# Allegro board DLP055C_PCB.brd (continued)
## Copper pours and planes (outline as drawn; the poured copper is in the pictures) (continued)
P1P8V on LY3: 183.64,48.77 175.98,48.77 173.67,46.46 173.67,42.67 173.88,42.47 173.88,42.21 172.73,41.07 170.12,41.07 168.44,42.75 168.44,53.59 178.83,63.98 178.83,84.38 178.12,85.09 160.34,85.09 159.5,85.93 159.5,90.17 160.31,90.98 161.56,90.98 161.63,90.91 165.52,90.91 166.7,92.08 166.7,103.84 167.56,104.71 183.64,104.71
P1P8V on LY8_PLANE: 146.02,79.87 148.51,79.87 150.03,78.34 151.81,78.34 153.72,80.25 158.03,80.25 160.7,82.91 160.7,87.74 161.97,89.01 161.97,90.53 160.32,92.19 160.32,94.6 158.8,96.12 152.95,96.12 152.07,97.01 152.07,97.9 152.7,98.54 152.7,99.3 152.32,99.68 151.81,99.68 151.3,99.17 151.3,94.98 151.68,94.6 157.15,94.6 158.03,93.71 158.03,91.04 155.62,88.63 155.62,87.74 157.4,85.96 157.4,83.55 155.11,81.26 150.29,81.26 149.4,82.15 149.4,83.3 149.27,83.42 144.83,83.42 143.94,84.31 143.94,86.34 147.11,89.52 147.11,90.28 146.6,90.79 145.97,90.79 145.08,89.9 143.43,89.9 143.3,90.03 143.3,91.3 145.33,93.33 145.33,94.09 144.45,94.98 143.05,94.98 141.3,93.23 141.3,80.65 138.86,78.22 138.86,68.08 139.62,67.32 141.55,67.32 145.36,71.13 145.36,79.21
P1P15V on TOP: 167.37,58.27 167.37,67.44 167.35,67.46 158.46,67.46 158.33,67.34 158.33,61.11 158.69,60.76 163.94,60.76 164.63,60.07 164.63,58.45 164.81,58.27
P1P15V on TOP: 146.15,80.32 159.28,80.32 160.42,81.47 160.42,96.35 158.95,97.82 148.48,97.82 147.62,96.96 147.62,94.14 148.48,93.28 155.37,93.28 155.83,92.82 155.83,84.9 155.47,84.54 153.72,84.54 153.62,84.64 147.85,84.64 146.15,82.94
P1P15V on BOTTOM: 165.53,52.69 166.29,52.69 166.67,53.07 166.67,54.97 167.18,55.48 173.27,55.48 173.53,55.74 173.53,56.12 170.99,58.66 170.23,58.66 168.96,59.93 168.96,65.01 166.54,67.42 161.72,67.42 158.67,64.37 158.67,61.07 159,60.74 163.22,60.74 165.4,58.56 165.4,52.82
P1P15V on LY7_PLANE: 145.86,59.94 164.78,59.94 166.29,61.45 166.29,105.52 161.57,110.24 151.32,110.24 141.67,100.58 141.67,87.63 142.83,86.47 146.73,86.47 147.11,86.85 147.11,87.11 146.86,87.36 146.22,87.36 145.08,88.5 145.08,90.28 149.67,94.87 154.46,94.87 154.99,94.34 154.99,91.17 155.62,90.53 157.29,90.53 157.53,90.3 157.53,89.39 156.76,88.63 155.49,88.63 154.29,87.42 154.29,77.14 150.18,73.03 139,73.03 137.86,71.88 137.86,67.94
P1P15V_BST on TOP: 159.83,54.79 159.83,56.54 159.6,56.77 158.92,56.77 158.92,54.94 159.07,54.79
P1P15V_FET on BOTTOM: 167.3,55.17 173.37,55.17 173.55,54.99 173.55,54.53 173.39,54.38 167.27,54.38 167.14,54.51 167.14,55.02
P1P15V_SW on TOP: 160.64,55.09 160.64,56.9 161.15,57.4 163.49,57.4 163.66,57.58 163.66,60.07 163.59,60.15 158.41,60.15 158.33,60.07 158.33,57.51 158.51,57.33 159.42,57.33 159.98,56.77 159.98,55.09
P1P21V on TOP: 83.64,54.31 93.62,54.31 96.06,56.75 96.06,80.88 100.03,84.86 100.03,87.5 98.47,89.06 96.34,89.06 90.47,83.19 90.47,57.11 89.89,56.52 83.71,56.52 83.64,56.45
P1P21V on BOTTOM: 159.88,81.91 159.88,87.56 157.85,89.59 157.85,90.14 158.2,90.48 159.55,90.48 159.88,90.82 159.88,97.86 158.92,98.81 140.15,98.81 134.18,92.84 134.18,82.8 134.75,82.23 137,82.23 137.38,81.85 139.47,81.85 139.47,85.89 140.03,86.45 141.32,86.45 141.91,85.86 141.91,85.4 140.46,83.96 140.46,81.85 148.87,81.85 148.87,85.4 147.98,85.4 147.39,85.99 147.39,92.85 147.9,93.35 154.22,93.35 154.71,92.87 154.71,85.18 154.15,84.62 152.4,84.62 152.4,80.3 158.26,80.3
P1P21V on LY7_PLANE: 137.35,82.8 137.35,78.99 138.49,77.85 144.34,77.85 147.75,81.26 147.75,87.36 147.49,87.61 146.35,87.61 145.48,88.49 145.48,90.3 149.67,94.49 154.34,94.49 154.73,94.09 154.73,90.53 154.99,90.28 156.76,90.28 157.02,90.03 157.02,89.65 156.51,89.14 154.48,89.14 153.84,88.5 153.84,77.98 149.65,73.79 131.76,73.79 128.97,76.58 128.97,81.41 125.92,84.45 96.84,84.45 96.46,84.84 96.46,89.53 96.96,90.04 130.11,90.04
P2P5V on TOP: 49.2,79.87 50.97,79.87 51.23,80.12 51.23,83.17 50.21,84.18 48.56,84.18 48.05,83.68 48.05,82.03 49.2,80.88
P2P5V on TOP: 84.12,58.15 87.8,58.15 88.57,58.91 88.57,76.06 88.06,76.56 86.53,76.56 86.15,76.18 86.15,75.17 86.79,74.53 86.79,66.91 82.72,62.85 82.72,59.55
P2P5V on LY3: 87.17,73.26 87.93,73.26 88.82,74.15 88.82,75.55 87.93,76.44 84.63,76.44 83.87,75.68 59.1,75.68 50.59,84.18 48.18,84.18 47.67,83.68 47.67,82.41 57.2,72.88 86.79,72.88
P3P3V on TOP: 51.74,82.79 53.89,82.79 54.02,82.91 54.02,83.93 55.16,85.07 55.16,86.6 54.53,87.23 52.75,87.23 51.74,86.22 50.21,86.22 50.08,86.09 50.08,84.95 51.74,83.3
P3P3V on LY8_PLANE: 0.76,150.59 65.96,150.59 66.1,150.45 66.8,150.45 66.94,150.59 69.95,150.59 70.09,150.45 70.63,150.45 70.77,150.59 78.99,150.59 78.99,148.99 81.36,148.99 81.36,150.59 83.74,150.59 83.74,148.99 86.11,148.99 86.11,150.59 187.34,150.59 187.34,0.76 0.76,0.76 0.76,17.71 1.11,18.06 1.11,19.95 0.76,20.3 0.76,42.66 0.94,42.83 0.94,45.02 0.76,45.2
P3P3V_SB on TOP: 87.31,124.79 87.31,123.93 87.24,123.85 87.24,123.14 86.7,122.61 80.94,122.61 80.68,122.35 80.68,116.15 81.34,115.49 87.97,115.49 88.02,115.54 88.02,118.57 87.92,118.67 87.92,120.42 88.15,120.65 88.15,123.29 87.59,123.85 87.59,124.79
P3P3V_SB on TOP: 167.02,133.45 168.47,133.45 169.02,134.01 169.02,137.24 168.74,137.52 167.25,137.52 166.79,137.06 166.79,133.68
P3P3V_SB on LY7_PLANE: 2.35,2.63 2.35,146.05 6.41,150.11 77.91,150.11 78.99,149.04 78.99,148.99 79.04,148.99 91.63,136.4 91.63,69.92 110,51.55 163.37,51.55 174.94,63.12 174.94,111.25 165.93,120.27 165.93,136.4 166.56,137.03 169.48,137.03 170.62,135.89 170.62,130.94 171.51,130.05 177.61,130.05 185.74,121.92 185.74,2.63
USB_AUX on TOP: 86.58,127 86.58,128.22 85.99,128.8 85.99,129.77 85.79,129.97 82.64,129.97 82.61,129.95 82.61,128.14 82.92,127.84 85.33,127.84 86.17,127
USB_SW on TOP: 86.6,124.82 80.68,124.82 80.68,122.89 85.36,122.89 85.56,123.09 85.56,123.95 85.79,124.18 86.6,124.18
USB_VBUS on TOP: 87.08,127 87.08,128.63 88.15,129.69 88.15,138.99 87.9,139.24 85.59,139.24 85.2,138.86 85.2,130.99 86.22,129.97 86.22,129.01 86.86,128.37 86.86,127
N30120583 on TOP (solid shape): 76.63,57.83 76.63,57.21 76.81,57.03 78,57.03 81.26,53.78 85.37,53.78 87.88,51.27 87.88,47.2 82.5,47.2 81.8,47.9 81.8,50.97 76.69,56.08 75.29,56.08 73.96,57.41 73.96,57.42 73.68,57.72 73.27,57.64 73.09,57.64 73.02,57.71 71.97,57.71 71.89,57.78 71.89,57.89 71.92,57.91 72.94,57.91 73.29,58.26 76.2,58.26
N30120672 on TOP (solid shape): 74.43,55.8 76.1,55.8 79.14,52.76 79.14,51.29 76.97,51.29 73.27,54.99 73.27,56.41 72.96,56.72 71.67,56.72 71.62,56.77 71.62,56.9 71.64,56.92 73.32,56.92
N30120689 on TOP (solid shape): 72.66,54.91 76,51.57 76,51.03 76.07,50.96 76.61,50.96 77.07,50.5 77.87,50.5 78.84,49.54 78.84,45.34 78.78,45.24 78.67,45.26 77.97,44.92 78.67,44.58 78.78,44.59 78.84,44.5 78.84,44.25 78.78,44.16 78.68,44.16 77.99,43.81 78.68,43.47 78.78,43.47 78.84,43.38 78.84,40.12 78.13,39.4 77.06,39.4 76.35,40.12 76.35,48.09 74.14,50.3 73.46,50.3 72.61,51.16 72.61,53.75 71.36,54.99 71.36,56.29 71.46,56.39 72.66,56.39
N30120771 on TOP: 82.98,39.61 90.09,39.61 90.47,39.99 90.47,41.89 89.84,42.53 83.61,42.53 83.1,43.04 81.96,43.04 81.58,42.66 81.58,41
N30121099 on TOP (solid shape): 79.8,62.34 78.42,60.95 78.38,60.97 77.92,60.87 77.83,60.41 77.84,60.37 77.75,60.28 75.99,60.28 75.91,60.2 74.42,60.2 74.41,60.2 74.24,60.24 74.07,60.2 74.06,60.2 71.74,60.2 71.74,60.43 72.91,60.43 73.04,60.56 73.58,60.56 75.44,62.42 75.46,62.43 75.66,62.54 75.78,62.75 75.78,62.76 76.63,63.61 79.8,63.61
N30121105 on TOP (solid shape): 82.93,56.55 82.93,54.57 82.7,54.34 81.43,54.34 80.23,55.54 80.69,55.54 80.69,55.48 80.7,55.42 80.72,55.36 80.74,55.31 80.77,55.26 80.81,55.21 80.85,55.17 80.9,55.14 80.95,55.11 81.01,55.09 81.07,55.08 81.13,55.08 81.18,55.08 81.24,55.09 81.3,55.11 81.35,55.14 81.4,55.17 81.44,55.21 81.48,55.26 81.51,55.31 81.53,55.36 81.55,55.42 81.56,55.48 81.56,55.54 81.55,55.6 81.53,55.65 81.51,55.71 81.48,55.76 81.44,55.8 81.4,55.84 81.35,55.88 81.3,55.91 81.24,55.93 81.18,55.94 81.13,55.94 81.07,55.94 81.01,55.93 80.95,55.91 80.9,55.88 80.85,55.84 80.81,55.8 80.77,55.76 80.74,55.71 80.72,55.65 80.7,55.6 80.69,55.54 80.23,55.54 78.25,57.51 77.01,57.51 77.01,59.04 77.92,59.95 79.52,59.95
N30121238 on TOP: 52.88,65.01 55.29,65.01 55.67,65.39 55.67,67.17 50.59,72.25 50.59,73.14 50.34,73.39 49.83,73.39 49.58,73.14 49.58,68.31
N30121264 on TOP: 42.97,65.01 47.93,65.01 48.69,65.77 48.69,69.33 47.93,70.09 45.51,70.09 42.97,67.55
N30121264 on BOTTOM: 46.66,66.79 56.56,66.79 57.58,67.8 63.04,67.8 65.07,65.77 65.58,65.77 65.83,66.02 65.83,66.91 62.53,70.21 47.67,70.21 46.15,68.69 46.15,67.29
N30121280 on TOP: 49.7,74.53 50.47,74.53 50.97,75.04 50.97,78.47 51.1,78.6 51.1,79.23 50.97,79.36 49.2,79.36 48.94,79.1 48.94,78.6 49.32,78.22 49.32,75.42 49.7,75.04
N30121351 on TOP (solid shape): 72.5,43.38 72.5,41.65 77,37.15 77,33.22 76.8,33.01 76.01,33.01 70.88,38.14 70.88,43.55 71.26,43.93 71.95,43.93
N30121367 on TOP (solid shape): 53.39,78.6 53.39,77.86 54.66,76.59 54.66,72.22 57.12,69.76 61.51,69.76 62.3,68.97 62.94,68.97 62.94,68.03 56.18,68.03 51.74,72.48 51.74,77.3 52.37,77.94 52.37,78.65 53.34,78.65
N30121469 on TOP (solid shape): 80.66,34.52 80.66,32.97 80.23,32.54 78.83,32.54 77.64,33.73 77.64,34.47 77.89,34.72 80.45,34.72
N30121485 on TOP (solid shape): 70.62,49.83 70.62,48.89 70.66,48.85 70.66,46.15 70.07,45.57 70.07,39.52 66.35,35.8 61.59,35.8 61.59,37.04 67.73,43.18 67.73,44.85 68.54,45.66 68.74,45.66 69.69,46.62 69.69,48.93 69.64,48.98 69.64,50.5 69.95,50.5
N30121491 on TOP (solid shape): 64.83,74.77 64.83,71.62 66.18,70.27 67.17,70.27 67.83,69.61 67.83,67.89 67.74,67.79 67.74,65.52 67.62,65.41 67.62,65.23 67.62,65.22 67.62,64.81 67.46,64.65 67.46,63.1 67.38,63.03 67.26,63.15 67.26,64.78 67.31,64.99 67.26,65.2 67.26,66.28 66.28,67.25 66.28,68.62 62.04,72.86 62.04,75.02 62.12,75.1 64.5,75.1
N30121519 on TOP (solid shape): 70.35,53.13 70.42,53.22 70.53,53.2 72.28,51.44 72.28,45.31 71.87,44.9 71.21,44.9 70.9,45.2 70.9,45.86 71.29,46.25 71.29,50.06 71.11,50.23 71.08,50.33 71.15,50.4 71.51,51.33 70.53,51.47 70.42,51.45 70.35,51.55
N30121523 on TOP (solid shape): 66.49,66.71 66.49,65.19 66.49,65.18 66.44,64.99 66.49,64.8 66.49,64.79 66.49,63 66.44,62.95 66.37,62.95 66.26,63.05 66.26,64.58 66.15,64.69 66.15,66.04 64.18,68 63.83,68 63.83,68.94 64.26,68.94
N30122241 on TOP (solid shape): 58.92,53.68 61.79,53.68 61.79,52.86 60.68,51.75 60.68,49.87 59.58,48.77 56.43,48.77 56.43,54.06 58.54,54.06
N30122253 on TOP (solid shape): 63.69,56.85 63.69,56.72 63.67,56.69 62.19,56.69 61.77,56.27 61.77,54.21 59.66,54.21 59.66,55.41 61.18,56.92 63.61,56.92
N30122298 on TOP (solid shape): 60.99,57.55 61.38,57.55 61.38,57.55 62.21,57.55 62.33,57.43 63.39,57.43 63.49,57.33 63.49,57.2 62.28,57.2 62.21,57.13 61.06,57.13 58.49,54.57 55.24,54.57 53.41,52.74 53.41,48.78 51.86,48.78 51.86,54.01 53.73,55.88 56.53,55.88 56.98,56.34 56.98,57.99 60.56,57.99
N30122422 on TOP (solid shape): 68.29,85.78 68.29,79.3 68.97,78.61 68.97,75.79 68.87,75.69 68.8,75.77 68.8,77.39 68.03,78.16 66.59,78.16 65.93,78.82 65.93,81.58 66.56,82.22 66.56,85.6 67.17,86.21 67.86,86.21
N30122488 on TOP (solid shape): 73.04,70.71 73.04,69.34 72.8,69.11 72.78,69.11 72.39,69 72.27,68.6 72.27,68.58 71.87,68.17 71.92,68.12 71.92,66.85 71.62,66.55 70.65,66.55 69.54,65.44 69.54,64.48 69.48,64.42 69.48,63.17 69.43,63.12 69.28,63.12 69.28,64.41 69.18,64.52 69.18,66.24 69.46,66.52 69.46,70.1 70.29,70.94 72.81,70.94
N30122494 on TOP (solid shape): outline of 85 points within 69.74,72.12 77.01,79.61
N30122512 on TOP (solid shape): 84.91,68.72 83.66,67.47 81.71,67.47 80.26,66.02 80.26,65.4 80.1,65.24 77.78,65.24 77.73,65.19 77.66,65.16 77.59,65.18 76.91,65.24 76.72,64.59 76.71,64.49 76.63,64.45 75.78,64.45 75.36,64.65 74.94,64.45 72.96,64.45 72.46,64.78 71.97,64.45 69.77,64.45 69.72,64.5 69.72,65.21 70.63,66.13 76.42,66.13 77.42,67.12 77.42,67.41 78.15,68.14 78.25,68.17 78.32,68.1 78.84,67.78 79.24,68.24 79.24,68.55 80.73,68.55 82.23,70.06 84.91,70.06
N30122563 on TOP (solid shape): 85.17,78.05 85.17,73.02 83.95,71.8 80.37,71.8 79.86,71.29 78.54,71.29 78.11,71.72 78.11,73.4 78.34,73.63 79.66,73.63 81.67,75.63 84.26,75.63 84.26,77.72 82.17,77.72 82.17,75.63 81.67,75.63 81.69,75.66 81.69,77.69 82.33,78.33 84.89,78.33
N30126115 on TOP: 12.74,41.35 17.16,41.35 19.34,43.54 21.07,43.54 21.37,43.84 21.37,45.44 21.76,45.82 21.76,46.53 21.6,46.69 19.67,46.69 17.13,44.15 13.91,44.15 12.38,42.62 12.38,41.71
N30126127 on TOP: 19.85,47.35 21.58,47.35 21.81,47.57 21.81,48.23 22.64,49.07 24.09,49.07 24.19,49.17 24.07,49.3 20.89,49.3 19.7,48.11 19.7,47.5
N30126180 on TOP: 14.57,62.28 17.08,62.28 19.32,64.52 22.85,64.52 23.33,65 26.45,65 26.86,65.41 26.86,65.81 26.25,66.42 16.12,66.42 14.36,64.67 14.36,62.48
N30126190 on TOP: 12.69,45.92 16.83,45.92 20.41,49.5 22.85,49.5 22.92,49.58 24.19,49.58 24.3,49.68 24.19,49.78 22.75,49.78 22.62,49.91 20.89,49.91 20.05,50.75 18.12,50.75 17.44,50.06 17.44,49.2 17.18,48.95 14.24,48.95 12.46,47.17 12.46,46.15
N30126220 on TOP: 29.6,55.55 29.6,58.13 29.13,58.61 28.65,58.61 28.32,58.94 28.32,61.17 28.06,61.43 28.06,63.25 24.63,63.25 24.63,61.81 25.88,60.56 25.88,58.81 26.16,58.53 27.28,58.53 27.66,58.15 28.05,58.15 29.4,56.79 29.4,55.6 29.45,55.55
N30126331 on TOP: 29.96,55.19 30.04,55.19 30.11,55.27 30.11,56.95 31.21,58.05 31.21,60.94 32.46,62.19 32.46,63.27 28.85,63.27 28.85,60.7 28.88,60.67 28.88,59.14 29.91,58.11 29.91,55.25
N30126337 on TOP: 28.66,72.26 24.3,72.26 23.84,71.81 23.84,69.22 25.06,68 29.12,68 29.12,65.35 29.38,65.1 31.79,65.1 32.32,65.63 32.32,66.14 31.1,67.36 31.1,69.82
N30126360 on TOP: 30.62,55.63 30.62,56.82 30.68,56.88 33.63,56.88 35.7,54.81 35.7,52.73 36,52.43 38.19,52.43 38.62,52.86 38.62,53.42 38.04,54 38.04,56.29 37.25,57.07 35.95,57.07 34.93,58.1 31.54,58.1 30.39,56.95 30.39,55.63 30.47,55.55 30.54,55.55
N30126390 on TOP: 36.11,39.95 39.08,39.95 39.69,40.56 39.69,42.72 37.43,44.98 37.43,47.68 38.8,49.05 38.8,50.04 38.32,50.52 35.8,50.52 35.42,50.14 35.42,40.64
N30128736 on TOP: 60.87,90.32 65.01,90.32 67.17,92.48 67.81,92.48 67.83,92.46 68.47,92.46 68.87,92.86 68.87,94.31 69.33,94.77 69.33,95.86 69.02,96.16 67.48,96.16 67.09,95.78 67.09,94.84 65.7,93.45 62.45,93.45 60.31,91.31 60.31,90.88
N30128748 on TOP: 67.6,96.88 68.9,96.88 70.62,98.6 72.56,98.6 72.68,98.73 72.58,98.83 68.87,98.83 67.35,97.31 67.35,97.13
N30128801 on TOP: 71.26,114.5 73.95,114.5 74.13,114.68 74.13,115.65 73.14,116.64 73.14,123.01 71.44,124.71 68.8,124.71 68.41,124.33 68.41,122.17 71.77,118.82 71.77,116.18 70.88,115.29 70.88,114.88
N30128811 on TOP: 61,94.92 63.56,94.92 67.63,98.98 69.08,98.98 69.18,99.09 72.4,99.09 72.5,99.19 72.38,99.31 68.97,99.31 68.52,99.77 63.97,99.77 63.44,99.24 63.44,98.45 62.47,97.49 61.18,97.49 60.06,96.37 60.06,95.86
N30128841 on TOP: 77.86,105.05 77.86,107.37 77.19,108.04 76.12,108.04 75.21,108.95 75.21,111.88 74.23,112.85 71.36,112.85 71.01,112.51 71.01,111.64 71.24,111.41 71.73,111.41 72.87,110.27 72.87,108.55 73.96,107.45 75.13,107.45 75.49,107.09 77.25,107.09 77.64,106.71 77.64,105.16 77.74,105.05
N30128952 on TOP: 78.35,105.13 78.35,107.87 79.29,108.81 79.29,111.23 79.87,111.81 79.87,112.24 79.46,112.65 77.08,112.65 76.54,112.12 76.54,109.42 78.17,107.8 78.17,105.16 78.27,105.05
N30128958 on TOP: 77.08,114.5 79.69,114.5 80.07,114.88 80.07,115.54 78.68,116.94 78.68,124.16 77.99,124.84 75.15,124.84 74.64,124.33 74.64,121.69 75.98,120.35 76.54,120.35 77.43,119.46 77.43,116.41 76.75,115.72 76.75,114.83
N30128978 on TOP: 78.73,104.8 78.78,104.8 78.88,104.9 78.88,106.43 79.01,106.55 81.72,106.55 83.55,104.72 85.28,104.72 85.79,105.23 85.79,107.19 85.2,107.77 85.2,111.38 84.95,111.63 84.21,111.63 83.78,111.2 83.78,107.95 83.12,107.29 78.93,107.29 78.65,107.01 78.65,104.98 78.63,104.95 78.63,104.9
N30129011 on TOP: 87.44,108.2 88.51,108.2 90.51,110.21 97.4,110.21 98.51,111.33 98.51,114.33 98.13,114.71 94.2,114.71 90.97,111.48 87.21,111.48 86.96,111.23 86.96,108.69
N30131580 on TOP: 35.99,128.89 39.04,128.89 39.54,129.4 39.54,131.68 39.92,132.06 46.66,132.06 49.96,128.76 53.39,128.76 53.89,129.27 53.89,131.68 54.4,132.19 54.4,133.84 56.94,136.38 56.94,137.4 56.69,137.65 55.67,137.65 54.4,136.38 49.2,136.38 48.05,137.52 48.05,141.21 47.67,141.59 47.04,141.59 46.27,140.83 46.27,136.76 44.5,134.98 37,134.98 35.99,133.97
N30131717 on TOP: 33.19,139.94 29.26,139.94 26.97,137.65 26.97,129.02 27.99,128 31.92,128 33.45,129.52 33.45,139.68
N30131961 on TOP: 29.38,140.7 33.45,140.7 38.02,145.27 38.02,148.45 37.26,149.21 29.89,149.21 27.73,147.05 27.73,142.35
N30131963 on TOP: 25.07,137.78 26.84,137.78 27.48,138.41 27.48,143.62 23.03,148.07 19.99,148.07 19.1,147.18 19.1,143.75
N30131977 on TOP: 63.16,128.17 64.2,128.17 64.63,128.6 64.63,130.66 65.19,131.22 66.69,131.22 66.99,131.52 66.99,134.06 66.46,134.59 63.56,134.59 62.57,133.6 62.57,130.17 63.03,129.72 63.03,128.3
N30132682 on TOP: 165.21,144.63 166,144.63 168.03,146.66 168.03,148.87 167.93,148.97 165.6,148.97 164.63,148.01 164.63,145.21
N30132740 on TOP: 164.27,142.7 164.27,140.05 164.51,139.81 164.51,139.18 164,138.67 164,133.33 164.26,133.08 164.26,131.94 164.69,131.5 165.38,131.5 165.38,132.8 165.78,133.21 165.78,137.78 166.04,138.03 168.86,138.03 169.13,138.3 169.13,142.88 168.36,143.64 165.21,143.64
N30132740 on BOTTOM: 162.38,129.5 163.52,129.5 164.87,128.15 166.98,128.15 166.98,130.13 166.54,130.56 165.83,130.56 165.38,131.02 165.38,135.01 164.77,135.62 164.38,135.62 163.95,135.19 163.95,132.55 162.1,130.69 162.1,129.78

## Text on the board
BOTTOM: LAYER 14 - BOTTOM
Ref Des/Silkscreen Bottom: LIBRA# DLP055
TOP: LAYER 1 - TOP
Ref Des/Silkscreen Top: FAN | DUAL CONTROLLER | MD1 | MD0 | ON | MD2 | USB | PARALLEL | CWI1 | VX1 | IIC0 | IIC1 | LOCK | CWI2 | TSTPTS | CWI0 | SPI1 | UART0 | FPDLINK | COIL1 | COIL2 | IIC2 | 12V FAN | DMD_HSSI0 | HEART  BEAT | FAULT | DMD_HSSI1 | ACTUATOR I/F | MADE IN U.S.A
L2_GND: LAYER 2 - GND PLANE
LY3: LAYER 3 - SIGNAL
LY4_GND: LAYER 4 - GND PLANE
LY5: LAYER 5 - SIGNAL
LY6_GND: LAYER 6 - GND PLANE
LY7_PLANE: LAYER 7 - PWR PLANE
LY8_PLANE: LAYER 8 - PWR PLANE
LY9_GND: LAYER 9 - GND PLANE
LY10: LAYER 10 - SIGNAL
LY11_GND: LAYER 11 - GND PLANE
LY12: LAYER 12 - SIGNAL
L13_GND: LAYER 13 - GND PLANE
DISPLAY_TOP: SOLDERPASTE TOP
User.6: SOLDERPASTE BOTTOM
User.7: LINE WIDTH (MILS) | LINE WIDTH/SPACING (MILS) | PCB MUST BEAR THE UL94V-0 UL REGISTERED MATERIAL ID NUMBER. | ACTUAL FABRICATION DATA MUST BE REVIEWED AND APPROVED. | 4. ALL BOARDS MUST MEET OR EXCEED UL94V-0 REQUIREMENTS. | 5. MINIMUM COPPER WALL THICKNESS OF PLATED-THRU | HOLES TO BE .001 INCH, WITH A MINIMUM | ANNULAR RING OF .001 INCH. | 6. OVERALL BOARD THICKNESS TO BE .076 +/- 10% | AND APPLIES AFTER ALL LAMINATION AND PLATING | PROCESSES, MEASURED FROM COPPER TO COPPER. | 7. MAX. WARP & TWIST TO BE .0075 INCHES PER INCH. | 8. ANY DESCREPENCY BETWEEN FABRICATION PRINT AND THE | FAB NOTES: | 2. THE PWB SHALL BE FABRICATED TO IPC-6012, | CLASS 2 AND WORKMANSHIP SHALL CONFORM TO | IPC-A-600, CLASS 2. CURRENT REVISIONS. | ROHS TO BE MARKED ON THE FINISHED BOARD. | 1. ALL DIMENSIONS ARE IN INCHES UNLESS | OTHERWISE NOTED.  ALL BOARD | OUTLINE DIMENSION TOLERANCES ARE +/- 10%. | BOARD OUTLINE DIMENSIONS ARE FOR REFERENCE ONLY | SEE GERBER FILES FOR EXACT BOARD OUTLINE DIMENSIONS. | 3. BOARD MATERIAL SHALL BE 180 Tg/340 Td ISOLA FR-370HR | OR EQUIVALENT, RoHS COMPLIANT AND LEAD FREE | ASSEMBLY CAPABLE.  BOARD MATERIAL SHALL | MEET OR EXCEED IPC-4101B. RoHS CERTIFICATE OF | CONFORMANCE SHALL BE DELIVERED WITH EACH LOT. | FABRICATION VENDOR IS ALLOWED TO INCREASE SOLDERMASK | COMPONENT PADS BY A MAXIMUM 1 MIL ON EACH SIDE OVER | THE COPPER PAD IN ORDER TO MEET TOOLING REQUIREMENTS | WHILE MAINTAINING WEBBING BETWEEN ADJACENT PADS. | 4. APPLY LPI SILKSCREEN OR EQUIVALENT PER THE ARTWORK | BOTH SIDES.  COLOR: WHITE. | NICKEL 100 MICROINCHES THK MIN, GOLD 2-6 MICROINCHES THK. | LAYER | 1 | 3 | 5 | 10 | 12 | 14 | 50 OHMS | 7.5 | 4.8 | IMPEDANCE REQUIREMENTS +/- 10% | 100 OHMS DIFFERENTIAL | 4.5/7.25 | 5/7 | 90 OHMS DIFFERENTIAL | 6/6 | 5.2/5.8 | PREPREG | CORE | 2 | 4 | 6 | 7 | 8 | 9 | 11 | 13 | DEFINITION | GND PLANE | SIGNAL | SOLDERMASK | SILKSCREEN | SPLIT PLANE | PREPREG/CORE | THICKNESS | (MILS) | 1 OZ | 1/2 OZ | Cu WT. | 0 | FAB DWG | + | 10% | 0.076 | - | TOP SIDE VIEW | LAYER STACKUP
User.15: DLPC7540EVM FORMATTER BOARD | DLP055 | TEXAS INSTRUMENTS | 16-APR 2021 | C
User.34: FIGURE | SIZE | 8.0 | 12.0 | 28.0 | 36.0 | 38.0 | 40.0 | 42.0 | 45.0 | 50.0 | 63.0 | 90.0 | 126.0 | 59.0 | 135.0 | 33.5x25.6 | 59.06x32.68 | 118.11x40.0 | 140.0x40.0 | 300.0x100.0 | DRILL CHART: TOP to BOTTOM | ALL UNITS ARE IN MILS | TOLERANCE | +0.0/-8.0 | +0.0/-12.0 | +3.0/-3.0 | +2.99/-2.99 | PLATED | NON-PLATED | QTY | 2451 | 35 | 127 | 4 | 22 | 41 | 156 | 7 | 24 | 34 | 2 | 1
